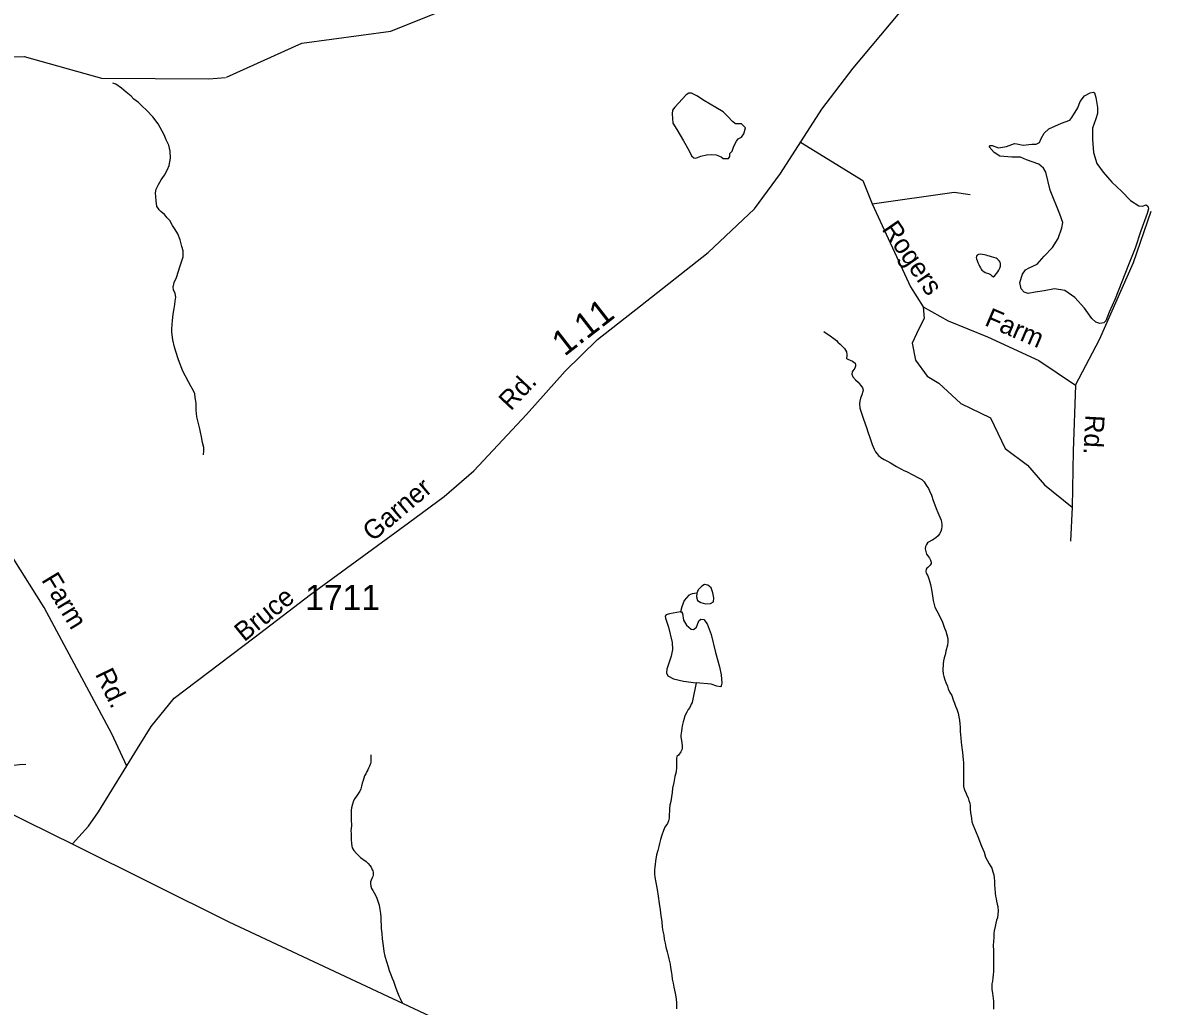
# Model space of a CAD drawing. Extents: x 2056842 to 2160602, y 826753 to 1016856.
# Drawn here: x 2109914 to 2115543, y 837119 to 842001 of the extents above; entities that cross this region are included whole.
import ezdxf

# ---------------------------------------------------------------- set-up
doc = ezdxf.new("R2010")
doc.units = 0
for name, color, linetype in [('Exist Boundary Political CountyLine', 7, 'Continuous'), ('Exist Hydrographic Misc Water Feature', 7, 'Continuous'), ('Exist Hydrographic Pond Under 1500 Sq Ft', 7, 'Continuous'), ('Exist Road Non-System Type 51', 7, 'Continuous'), ('Exist Road Non-System Type 51 Label', 7, 'Continuous'), ('Exist Road Secondary Mileage Hundredths English Label', 7, 'Continuous'), ('Exist Road Secondary Type 51 Attributed', 7, 'Continuous'), ('Exist Road Secondary Type 51 Label', 7, 'Continuous'), ('Exist Road Secondary Type 51 Number Label', 7, 'Continuous')]:
    doc.layers.add(name, color=color, linetype=linetype)

msp = doc.modelspace()

# ---------------------------------------------------------------- linework, layer by layer
at = {"layer": 'Exist Boundary Political CountyLine'}
msp.add_lwpolyline([(2102162, 841868.8), (2110170.3, 837920.8), (2110936.9, 837538.4), (2113401.3, 836382.3), (2113845.4, 836165.5), (2114325.1, 835933.8), (2116216.5, 835032.6), (2117012.9, 834657.8), (2117168.3, 834572.5), (2123082.8, 831883.9), (2127502, 829978.1), (2130799, 828547.5), (2131147.1, 828402.1), (2131915.4, 828068), (2133839.4, 827270.1)], dxfattribs=at)
at = {"layer": 'Exist Hydrographic Misc Water Feature'}
for points in [[(2110926, 841729.7), (2111299.8, 841899.1), (2111740.9, 841958.9), (2112073.9, 842093.2), (2112489.9, 842202.7), (2112679.8, 842553.2)], [(2106382.6, 839788.1), (2106958.3, 840341), (2107084, 840450.4), (2107517, 840661.4), (2107624.9, 840760.8), (2108581.1, 841354.7), (2109379.9, 841758.2), (2109628.9, 841831.8), (2109920.9, 841832.4), (2110304.9, 841726), (2110837.8, 841721.6), (2110920.5, 841729.2)], [(2110811.1, 839855.1), (2110813.1, 839875.1), (2110813.1, 839892.9), (2110807, 839917), (2110801, 839945.1), (2110796.5, 839968.9), (2110792.8, 839984.8), (2110778.7, 840045), (2110774.6, 840076.9), (2110774.6, 840113), (2110770.3, 840140.8), (2110768.2, 840159), (2110762.1, 840172.9), (2110748.3, 840196.9), (2110736.2, 840218.6), (2110708.3, 840270.7), (2110687.8, 840326.6), (2110673.5, 840368.5), (2110667.5, 840390.5), (2110659.5, 840426.6), (2110653.4, 840464.5), (2110653.6, 840480.2), (2110655, 840502.3), (2110657.1, 840522.3), (2110661.2, 840554.6), (2110665.1, 840582.4), (2110668.8, 840602.5), (2110671, 840618.4), (2110673.1, 840638.4), (2110671, 840656.5), (2110662.8, 840674.4), (2110660.6, 840688.6), (2110666.3, 840710.4), (2110676.6, 840736.5), (2110696, 840794.3), (2110710.2, 840838.5), (2110710.2, 840868.5), (2110704, 840890.6), (2110696.2, 840922.5), (2110683.7, 840952.4), (2110670, 840974.4), (2110657.9, 840994.5), (2110643.7, 841018.1), (2110631.4, 841032.1), (2110617.7, 841048), (2110599.5, 841064.2), (2110591.5, 841072.3), (2110585.5, 841080.1), (2110579.6, 841087.9), (2110575.5, 841116.1), (2110573.2, 841156.2), (2110576.9, 841173.9), (2110587.4, 841197.9), (2110601.3, 841220.1), (2110617.1, 841244.1), (2110632.9, 841272.2), (2110640.9, 841292.5), (2110646.8, 841328), (2110646.6, 841362.2), (2110638.8, 841392.2), (2110626.5, 841420), (2110616.5, 841444.2), (2110586.3, 841497.9), (2110560.1, 841534), (2110530.1, 841564), (2110505.5, 841587.6), (2110487.9, 841603.7), (2110465.8, 841621.6), (2110452, 841635.5), (2110427.6, 841655.4), (2110403.8, 841675.3), (2110375.7, 841695.3), (2110361.8, 841701.1)], [(2115434, 840882.2), (2115400.9, 840798.4), (2115367.9, 840714.6), (2115334.8, 840630.8), (2115305.1, 840564.6), (2115288.5, 840521.6), (2115277.5, 840510.6), (2115257.7, 840508.4), (2115238.9, 840515), (2115219.1, 840532.6), (2115182.7, 840584.5), (2115134.2, 840636.3), (2115084.6, 840671.6), (2115033.9, 840679.3), (2114982.1, 840670.5), (2114938, 840662.8), (2114902.8, 840657.2), (2114882.9, 840662.8), (2114867.5, 840680.4), (2114862, 840711.3), (2114874.1, 840752.1), (2114889.5, 840774.1), (2114907.2, 840784.1), (2114947.9, 840801.7), (2114982.1, 840841.4), (2115022.9, 840884.4), (2115051.5, 840929.6), (2115070.3, 840982.6), (2115074.7, 841009), (2115059.3, 841051), (2115011.9, 841170.1), (2114989.8, 841259.4), (2114978.8, 841279.2), (2114955.7, 841298), (2114895, 841320), (2114864.2, 841333.3), (2114821.2, 841333.3), (2114761.7, 841338.8), (2114734.1, 841356.4), (2114709.9, 841384), (2114714.3, 841391.7), (2114724.2, 841390.6), (2114756.2, 841379.6), (2114795.8, 841386.2), (2114834.4, 841400.6), (2114846.5, 841399.5), (2114878.5, 841392.8), (2114920.4, 841398.3), (2114942.4, 841397.2), (2114959, 841406.1), (2114967.8, 841425.9), (2114982.1, 841452.4), (2115005.3, 841473.3), (2115068.1, 841502), (2115108.9, 841516.4), (2115119.9, 841530.7), (2115148.5, 841578.1), (2115160.7, 841610.1), (2115181.6, 841637.7), (2115210.3, 841653.1), (2115225.7, 841656.4), (2115231.2, 841652), (2115238.9, 841628.8), (2115246.6, 841579.2), (2115246.6, 841550.5), (2115238.9, 841523), (2115222.4, 841476.6), (2115221.3, 841421.5), (2115226.8, 841356.4), (2115243.3, 841301.3), (2115274.2, 841258.3), (2115317.2, 841208.7), (2115366.8, 841162.3), (2115410.9, 841118.2), (2115451.6, 841091.8), (2115470.4, 841089.6), (2115488, 841096.2), (2115496.8, 841089.6), (2115499, 841076.3), (2115493.5, 841053.2), (2115461.6, 840968.2), (2115434, 840882.2)], [(2114749, 840828), (2114743.3, 840831.3), (2114732.4, 840835.4), (2114721.2, 840839.1), (2114711.5, 840841.8), (2114703.3, 840843.5), (2114693.9, 840846.1), (2114685.3, 840848.3), (2114676.2, 840850), (2114664.8, 840851.8), (2114657, 840850.9), (2114649, 840847.2), (2114645.7, 840842.1), (2114645.3, 840834.8), (2114646.9, 840828.9), (2114649.4, 840820.8), (2114653.7, 840810.8), (2114657.6, 840800.9), (2114661.5, 840791.8), (2114665.8, 840784.6), (2114669.7, 840776.8), (2114673, 840771.8), (2114677.3, 840768.7), (2114682.2, 840765.2), (2114690, 840761.1), (2114693.9, 840759.3), (2114706, 840755.1), (2114715.2, 840751.6), (2114721.2, 840746.2), (2114725.9, 840742.3), (2114730.2, 840739.6), (2114734.3, 840741), (2114739.8, 840749.1), (2114746, 840755.9), (2114751.7, 840763.9), (2114757.2, 840772), (2114761.8, 840781.5), (2114765.2, 840792.3), (2114766.1, 840799.5), (2114765.7, 840805.2), (2114763.4, 840812.1), (2114759.3, 840818), (2114755.4, 840821.8), (2114749, 840828)], [(2113888.5, 840468.7), (2113920.5, 840446.7), (2113938.7, 840433.4), (2113951, 840423.4), (2113959, 840414.9), (2113969.1, 840404.9), (2113979.1, 840395.7), (2113985.3, 840389.9), (2113991, 840383.3), (2114001.1, 840367.2), (2114003.5, 840353.4), (2114002.7, 840345.8), (2114001.3, 840337.9), (2114001.9, 840333.8), (2114005.4, 840332), (2114011.9, 840329.4), (2114019.3, 840325.9), (2114031.8, 840319.9), (2114043.7, 840311.2), (2114045.6, 840304.9), (2114045.8, 840295.9), (2114042.1, 840285.9), (2114038.4, 840279.5), (2114033.1, 840273.1), (2114030, 840267.5), (2114028.5, 840255.9), (2114032.4, 840243.6), (2114046, 840228.5), (2114058.5, 840216.1), (2114064.6, 840210.2), (2114072.8, 840200.1), (2114081, 840188.3), (2114083.3, 840178.7), (2114083.1, 840170.6), (2114077.3, 840154), (2114071, 840136.3), (2114067.5, 840122.2), (2114065.4, 840109.9), (2114067.7, 840087.7), (2114074.1, 840068), (2114084.5, 840038.1), (2114094.6, 840010.2), (2114100.7, 839990.6), (2114106.7, 839970.6), (2114116.9, 839942.3), (2114123.5, 839922.6), (2114129.4, 839907.1), (2114137.8, 839884.7), (2114141.7, 839876.5), (2114145.8, 839870.6), (2114151.8, 839863.1), (2114159.8, 839853), (2114171.3, 839842.7), (2114187.9, 839832.9), (2114204.1, 839824.8), (2114219.9, 839815.9), (2114250.2, 839797.9), (2114264.6, 839790.1), (2114274.6, 839784.1), (2114286.3, 839778.2), (2114298.6, 839772.4), (2114330.8, 839756.9), (2114358.9, 839742.1), (2114375.7, 839733.1), (2114387, 839721.2), (2114396.8, 839704.7), (2114407.5, 839688.9), (2114413.2, 839677.1), (2114423.5, 839654.9), (2114431.9, 839629.2), (2114440.3, 839607.6), (2114446.2, 839589.7), (2114454.4, 839569.8), (2114470.4, 839531.7), (2114474.9, 839511.9), (2114474.9, 839499.4), (2114472.9, 839487.5), (2114469.2, 839475.8), (2114463.5, 839463.7), (2114455.3, 839453.2), (2114445.2, 839443.8), (2114435.2, 839437.2), (2114427.8, 839433), (2114423.5, 839430.8), (2114407.5, 839423.1), (2114403.8, 839418.8), (2114397.6, 839410.8), (2114393.5, 839401.3), (2114391.9, 839389), (2114394.1, 839376.5), (2114398.2, 839363.3), (2114404.2, 839355.1), (2114408.3, 839349.2), (2114412.4, 839343.3), (2114418.3, 839333.4), (2114420.6, 839323.4), (2114420.8, 839316.9), (2114416.1, 839307.4), (2114410.3, 839301), (2114404.6, 839297)], [(2114404.6, 839297), (2114400.1, 839292.8), (2114397.2, 839288), (2114394.8, 839279), (2114397, 839268.9), (2114405.4, 839255.1), (2114412.2, 839235), (2114417.3, 839212.7), (2114421.8, 839195.4), (2114424.7, 839177.5), (2114428, 839156.7), (2114432.1, 839132.9), (2114436.2, 839113.3), (2114440.1, 839099.3), (2114448.7, 839081.7), (2114469.2, 839043.8), (2114477.2, 839025.5), (2114483.3, 839009.6), (2114487.4, 838995.6), (2114493.8, 838980), (2114499.7, 838961.7), (2114503.9, 838943.6), (2114503.9, 838928.2), (2114502, 838911.8), (2114494.8, 838881.7), (2114490.5, 838863.6), (2114486.6, 838848), (2114482.5, 838833.2), (2114481.3, 838818), (2114479.2, 838787.4), (2114481.3, 838769.3), (2114483.5, 838755.6), (2114489.9, 838739.6), (2114494, 838725.6), (2114502, 838707.3), (2114506.1, 838694.1), (2114514.1, 838676.2), (2114523.1, 838661.1), (2114530.3, 838640.5), (2114536.9, 838623.7), (2114542.8, 838608.2), (2114549, 838593.9), (2114555.3, 838574.2), (2114559.4, 838554.6), (2114561.3, 838538), (2114563.3, 838519.9), (2114565.6, 838504.6), (2114565.6, 838484.7), (2114566.8, 838466.6), (2114568.2, 838450.2), (2114570.1, 838430.4), (2114572.5, 838414.7), (2114576.8, 838378.7), (2114578.9, 838360.5), (2114580.9, 838342.4), (2114581.2, 838328.5), (2114581.4, 838318.8), (2114581.8, 838308.9), (2114581.4, 838296.4), (2114581.6, 838280.2), (2114581.6, 838264.8), (2114582, 838254.6), (2114582.2, 838242.4), (2114582.2, 838232.6), (2114582, 838218.5), (2114582.4, 838210.3), (2114586.5, 838192.2), (2114594.7, 838174.7), (2114598.6, 838164.8), (2114604.5, 838152.5), (2114609, 838140.9), (2114613.6, 838127.6), (2114615, 838112.8), (2114615, 838100.7), (2114617.2, 838078.4), (2114619.9, 838063), (2114621.5, 838050.6), (2114623.6, 838034.8), (2114628.1, 838020.8), (2114636.3, 838000.9), (2114644.5, 837981), (2114652.5, 837961.1), (2114671, 837913.2), (2114683.5, 837883.4), (2114691.3, 837859.5), (2114699.5, 837844), (2114709.9, 837825.4), (2114721.6, 837804.2), (2114728, 837785.8), (2114732.5, 837771.7), (2114734.5, 837756), (2114736.4, 837739.8), (2114736.4, 837721.6), (2114737, 837702), (2114739.2, 837682.2), (2114741.1, 837665.7), (2114743.6, 837652), (2114745.4, 837640.3), (2114749.5, 837626.3), (2114751.6, 837613.8)], [(2113258.7, 839169.4), (2113257.5, 839151.2), (2113262.4, 839132.9), (2113278.2, 839123.2), (2113302.5, 839115.9), (2113326.8, 839117.1), (2113341.4, 839126.9), (2113342.6, 839146.3), (2113338.9, 839170.6), (2113329.2, 839195), (2113313.4, 839209.6), (2113296.4, 839212), (2113283, 839204.7), (2113264.8, 839185.2), (2113258.7, 839169.4)], [(2113258.7, 839169.4), (2113235.6, 839165.8), (2113218.6, 839158.5), (2113196.7, 839132.9), (2113184.6, 839101.3), (2113177.3, 839077)], [(2113177.3, 839077), (2113122.6, 839066.1), (2113106.8, 839062.4), (2113101.9, 839055.1), (2113103.1, 839045.4), (2113118.9, 839000.4), (2113137.2, 838925), (2113138.4, 838889.7), (2113131.1, 838856.9), (2113109.2, 838792.4), (2113108, 838773), (2113114.1, 838758.4), (2113143.2, 838743.8), (2113193.1, 838731.6), (2113255.1, 838724.3)], [(2113177.3, 839077), (2113183.3, 839075.8), (2113187, 839068.5), (2113191.9, 839035.7), (2113207.7, 839010.1), (2113230.8, 838990.7), (2113242.9, 838989.4), (2113256.3, 839000.4), (2113268.4, 839032), (2113278.2, 839040.5), (2113292.7, 839038.1), (2113309.8, 839016.2), (2113330.4, 838963.9), (2113351.1, 838875.1), (2113371.7, 838803.4), (2113379, 838764.4), (2113382.7, 838721.9), (2113380.2, 838708.5), (2113375.4, 838703.6), (2113358.4, 838707.3), (2113329.2, 838717), (2113255.1, 838724.3)], [(2113255.1, 838724.3), (2113238.9, 838642.6), (2113237, 838634.4), (2113235, 838627), (2113231.1, 838618.6), (2113227.2, 838610.7), (2113223.3, 838602.4), (2113216.3, 838591.3), (2113209.6, 838578.9), (2113201.2, 838564.3), (2113197.5, 838554.8), (2113195.6, 838546.5), (2113191.5, 838530.1), (2113187.8, 838518), (2113186.2, 838509.8), (2113184.1, 838498.3), (2113181.9, 838484.5), (2113180.2, 838464.1), (2113180.2, 838454.3), (2113182.3, 838438.6), (2113184.5, 838426.1), (2113186.6, 838410.8), (2113186, 838399.8), (2113184.5, 838391.2), (2113178.8, 838381.9), (2113167.3, 838365.8), (2113159.9, 838358), (2113157.5, 838347.8)], [(2111641.3, 838366.9), (2111641.5, 838354.7), (2111641.5, 838344.9), (2111641.7, 838330.7), (2111639.9, 838324.5), (2111634.1, 838310.3), (2111630.5, 838300.7), (2111626.1, 838292.5), (2111622.3, 838284.5), (2111616.3, 838272.4), (2111610.6, 838262.8), (2111606.5, 838251.2), (2111602.6, 838238.8), (2111598.9, 838226), (2111594.8, 838212), (2111591.3, 838198.4), (2111589, 838190.2), (2111587.4, 838186), (2111579.4, 838176.2), (2111569.6, 838161.9), (2111561.6, 838149.7), (2111555.6, 838137.6), (2111550.1, 838121.8), (2111545.8, 838104.2), (2111544.1, 838091.9), (2111543.9, 838075.3), (2111544.1, 838061.4), (2111544.3, 838051.7), (2111544.5, 838037.5), (2111544.7, 838023.6), (2111544.7, 838013.9), (2111542.9, 837990.2), (2111543.1, 837976), (2111543.1, 837945.5), (2111545.4, 837927.8), (2111547.6, 837913.7), (2111549.3, 837905.3), (2111557.7, 837892.2), (2111570, 837876.2), (2111582.3, 837866.2), (2111590.3, 837857.7), (2111602.4, 837848.6), (2111618.2, 837836.8), (2111628.4, 837826.8), (2111636, 837816.7), (2111642.3, 837808.4), (2111646.7, 837800.9), (2111648.5, 837796.5), (2111650.6, 837791), (2111652.8, 837784.5), (2111652.6, 837778.5), (2111653, 837770.3), (2111651.6, 837762.4), (2111648.5, 837756.4), (2111643.2, 837744.2), (2111640.1, 837736.1), (2111639.3, 837726.5), (2111641.1, 837714.9), (2111645, 837702.5), (2111651.6, 837692.6), (2111664.1, 837670.8), (2111671.3, 837656), (2111676, 837641), (2111682.3, 837620.6), (2111686, 837599), (2111688.7, 837578.7), (2111690.3, 837561.3), (2111690.9, 837541), (2111691.8, 837523.4), (2111692.8, 837504.6), (2111695.3, 837480.7), (2111697.5, 837452.8), (2111702, 837419.2), (2111706.3, 837391), (2111711.2, 837367.1), (2111718.6, 837340.8), (2111726.8, 837315.3), (2111732.8, 837295.7), (2111739.1, 837279.7), (2111747.1, 837259), (2111753.5, 837243.4), (2111763.7, 837213.5), (2111769.7, 837195.5), (2111780.3, 837170), (2111786.3, 837157.3), (2111792, 837145.9), (2111797.8, 837134.5), (2111801.3, 837132.9)], [(2109930.2, 838318.5), (2109898, 838316.5), (2109870.3, 838314.2), (2109844.2, 838312.5), (2109822.5, 838312.1), (2109798.3, 838310.1), (2109774.1, 838308.1), (2109758.1, 838304), (2109730.4, 838297.7), (2109692.1, 838287.6), (2109668.3, 838279.5), (2109642.5, 838269.6), (2109616.2, 838255.7), (2109596.5, 838249.4), (2109576.7, 838245.5), (2109522.5, 838240.2)], [(2113157.5, 838347.8), (2113157.5, 838320.2), (2113158.1, 838306.3), (2113155.4, 838282.4), (2113150.3, 838259.6), (2113144.6, 838230.1), (2113138.6, 838201.8), (2113136.6, 838179.4), (2113133.5, 838157.5), (2113129.4, 838135.4), (2113125.5, 838117.3), (2113123.2, 838099.4), (2113122.6, 838085.3), (2113121.6, 838071.7), (2113122.2, 838061.8), (2113121.4, 838051.8), (2113118.5, 838039.7), (2113112.4, 838025.6), (2113108.3, 838019.3), (2113100.3, 838007.1), (2113092.7, 837991.6), (2113084.7, 837967.3), (2113078.7, 837947.1), (2113073, 837927.3), (2113069.5, 837911.2), (2113065.6, 837891.5), (2113059.3, 837870.9), (2113054.1, 837839.3), (2113052.1, 837822.9), (2113049.8, 837811.5), (2113048.2, 837793.5), (2113048.4, 837776.8), (2113050.9, 837759), (2113054.7, 837733.3), (2113061.3, 837698.6), (2113067.5, 837665.2), (2113071.8, 837628.8), (2113076.3, 837597.7), (2113080.6, 837567.1), (2113084.5, 837539.3), (2113086.5, 837511.3), (2113090.2, 837492.2), (2113094.3, 837471.6), (2113097.4, 837451.3), (2113101.7, 837431.2), (2113105.6, 837411.5), (2113112.2, 837389.4), (2113116.1, 837369.3), (2113120.2, 837353.7), (2113126.5, 837327.6), (2113128.6, 837311.9), (2113130.6, 837293.7), (2113134.3, 837272.5), (2113137.2, 837253.4), (2113141.1, 837233.7), (2113145.4, 837214), (2113151.5, 837184.2), (2113156.2, 837156.3), (2113158.5, 837134.1), (2113158.5, 837106.1)], [(2114751.6, 837613.8), (2114753.8, 837591.5), (2114752.2, 837576), (2114749.9, 837558), (2114746.2, 837546.1), (2114742.1, 837532), (2114738.4, 837514), (2114734.5, 837493.8), (2114732.7, 837479.9), (2114733.1, 837460), (2114731, 837439.6), (2114729, 837420), (2114729.8, 837396.4), (2114729.8, 837378.1), (2114729.8, 837365.9), (2114730, 837346), (2114730.4, 837325.7), (2114730, 837305.8), (2114730.2, 837292), (2114728.6, 837274), (2114726.7, 837260.1), (2114724.9, 837243.8), (2114722.8, 837229.9), (2114723.1, 837220.1), (2114722.8, 837201.8), (2114725.3, 837183.6), (2114727.4, 837169.9), (2114729.8, 837143.6), (2114730, 837129.4), (2114730, 837104.2)]]:
    msp.add_lwpolyline(points, dxfattribs=at)
at = {"layer": 'Exist Hydrographic Pond Under 1500 Sq Ft'}
msp.add_lwpolyline([(2113500.8, 841479), (2113480.4, 841499.4), (2113451.2, 841499.4), (2113435.1, 841509.6), (2113411.8, 841534.4), (2113389.9, 841557.8), (2113353.4, 841579.6), (2113296.5, 841613.2), (2113258.5, 841638), (2113232.2, 841651.1), (2113219.1, 841651.1), (2113206, 841642.4), (2113149, 841581.1), (2113137.4, 841566.5), (2113135.9, 841547.5), (2113140.3, 841502.3), (2113159.3, 841470.2), (2113192.8, 841414.8), (2113220.6, 841365.2), (2113232.2, 841340.4), (2113243.9, 841330.2), (2113254.1, 841328.7), (2113278.9, 841338.9), (2113306.7, 841344.8), (2113333, 841346.2), (2113354.8, 841344.8), (2113379.7, 841334.6), (2113389.9, 841327.3), (2113403, 841325.8), (2113416.2, 841327.3), (2113422, 841336), (2113422, 841350.6), (2113433.7, 841363.7), (2113442.4, 841387.1), (2113455.6, 841411.9), (2113464.3, 841423.6), (2113480.4, 841432.3), (2113492.1, 841448.4)], close=True, dxfattribs=at)
at = {"layer": 'Exist Road Non-System Type 51'}
msp.add_line((2115121.2, 839596.8), (2115111.9, 839427.4), dxfattribs=at)
for points in [[(2113773.7, 841407), (2114082.7, 841218), (2114128.4, 841101.6)], [(2114128.4, 841101.6), (2114535.5, 841159.8), (2114614.4, 841147.3)], [(2114128.4, 841101.6), (2114319.5, 840690.1), (2114381.8, 840590.3)], [(2115137.9, 840201.6), (2115256.2, 840428.2), (2115424.5, 840810.6), (2115512.8, 841065.2)], [(2114381.8, 840590.3), (2114387, 840533.1), (2114357.9, 840477), (2114326.8, 840410.5), (2114343.4, 840325.3), (2114401.6, 840246.3), (2114459.7, 840211), (2114568.8, 840110.2), (2114716.2, 840039.5), (2114788.9, 839887.8), (2114899, 839804.6), (2114984.2, 839707), (2115121.2, 839596.8)], [(2114381.8, 840590.3), (2114505.4, 840520.7), (2114700.6, 840441.7), (2114956.1, 840323.2), (2115137.9, 840201.6)], [(2115137.9, 840201.6), (2115125.4, 839873.2), (2115121.2, 839596.8)], [(2110430.5, 838311.3), (2110356.6, 838470.3), (2110020.1, 839098), (2109866.4, 839343.2)]]:
    msp.add_lwpolyline(points, dxfattribs=at)
at = {"layer": 'Exist Road Secondary Type 51 Attributed'}
msp.add_lwpolyline([(2110161.3, 837925.3), (2110240.8, 838012.5), (2110290.6, 838084.2), (2110484.3, 838398.6), (2110551.8, 838506.6), (2110666.1, 838648), (2111061.2, 838947.8), (2111342.6, 839162.9), (2111828.1, 839517.8), (2112005.7, 839648.8), (2112153.2, 839776.6), (2112414.4, 840055.6), (2112605.5, 840270.7), (2112765.4, 840428.7), (2112979.8, 840595.5), (2113315.3, 840860.5), (2113545.3, 841077.2), (2113674.1, 841251.8), (2113879.2, 841571.3), (2114035, 841775), (2114265.5, 842051.4)], dxfattribs=at)

# ---------------------------------------------------------------- texts
at = {"layer": 'Exist Road Non-System Type 51 Label'}
for s, rotation, p in [('Rogers', 304.5514, (2114173.6, 840975.7)), ('Farm', 336.7829, (2114681.7, 840500.6)), ('Rd.', 266.8336, (2115187.7, 840056)), ('Farm', 301.1334, (2110004.4, 839235)), ('Rd.', 295.872, (2110271.6, 838767.7))]:
    msp.add_text(s, height=95, rotation=rotation, dxfattribs=at).set_placement(p)
at = {"layer": 'Exist Road Secondary Mileage Hundredths English Label'}
msp.add_text('1.11', height=125, rotation=37.8751, dxfattribs=at).set_placement((2112602, 840341.3))
at = {"layer": 'Exist Road Secondary Type 51 Label'}
for s, rotation, p in [('Rd.', 46.7626, (2112335.4, 840070.6)), ('Garner', 40.3151, (2111650.7, 839421.6)), ('Bruce', 39.1827, (2111013.1, 838924.7))]:
    msp.add_text(s, height=95, rotation=rotation, dxfattribs=at).set_placement(p)
at = {"layer": 'Exist Road Secondary Type 51 Number Label'}
msp.add_text('1711', height=125, dxfattribs=at).set_placement((2111315.2, 839085.4))

doc.saveas('drawing.dxf')
